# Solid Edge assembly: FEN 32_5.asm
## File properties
Title: Zylinder
Author: bmolnar
Template: iso assembly.asm
Last saved by: bmolnar
Revision: 10
Application: Solid Edge
Username: bmolnar
Dokumentum tartalom típus: 1
Document Number: FEN 32/5
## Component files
Kolbenstange.par
Profilrohr.par
Kit_1.par
Kit_2.par
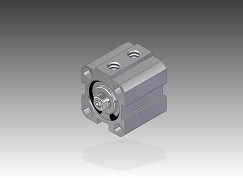
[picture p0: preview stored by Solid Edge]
